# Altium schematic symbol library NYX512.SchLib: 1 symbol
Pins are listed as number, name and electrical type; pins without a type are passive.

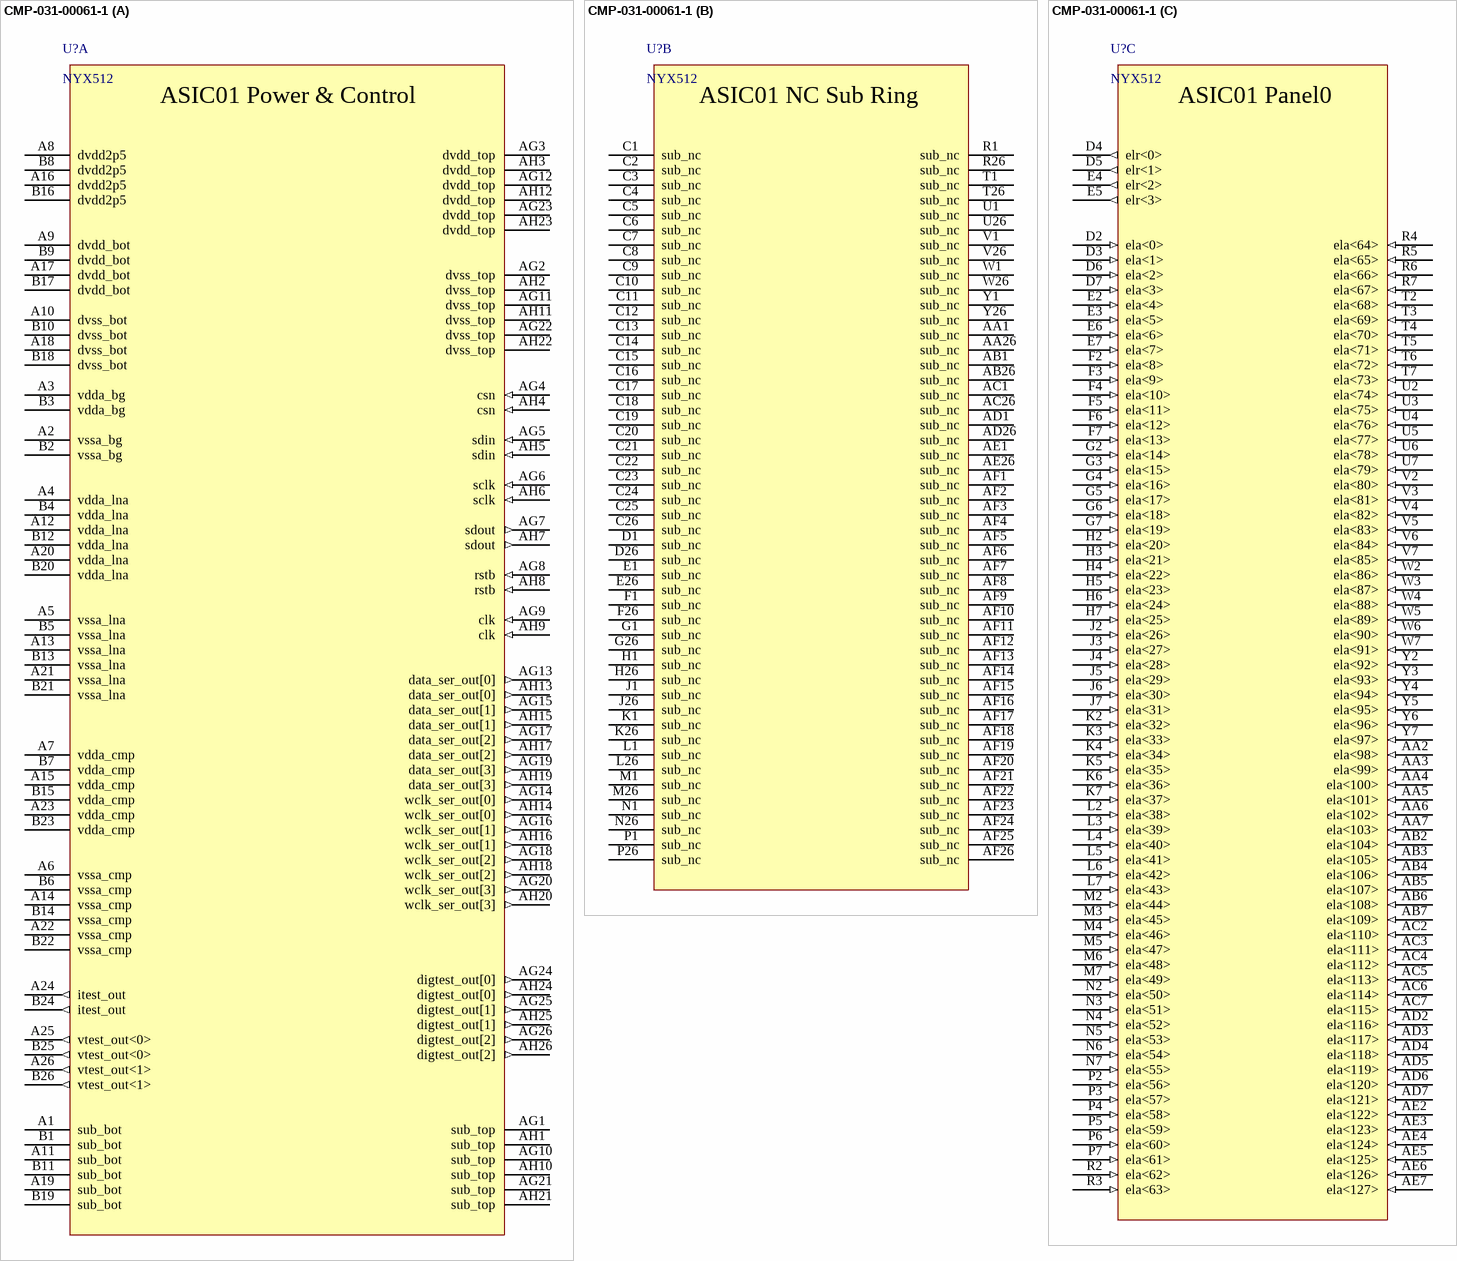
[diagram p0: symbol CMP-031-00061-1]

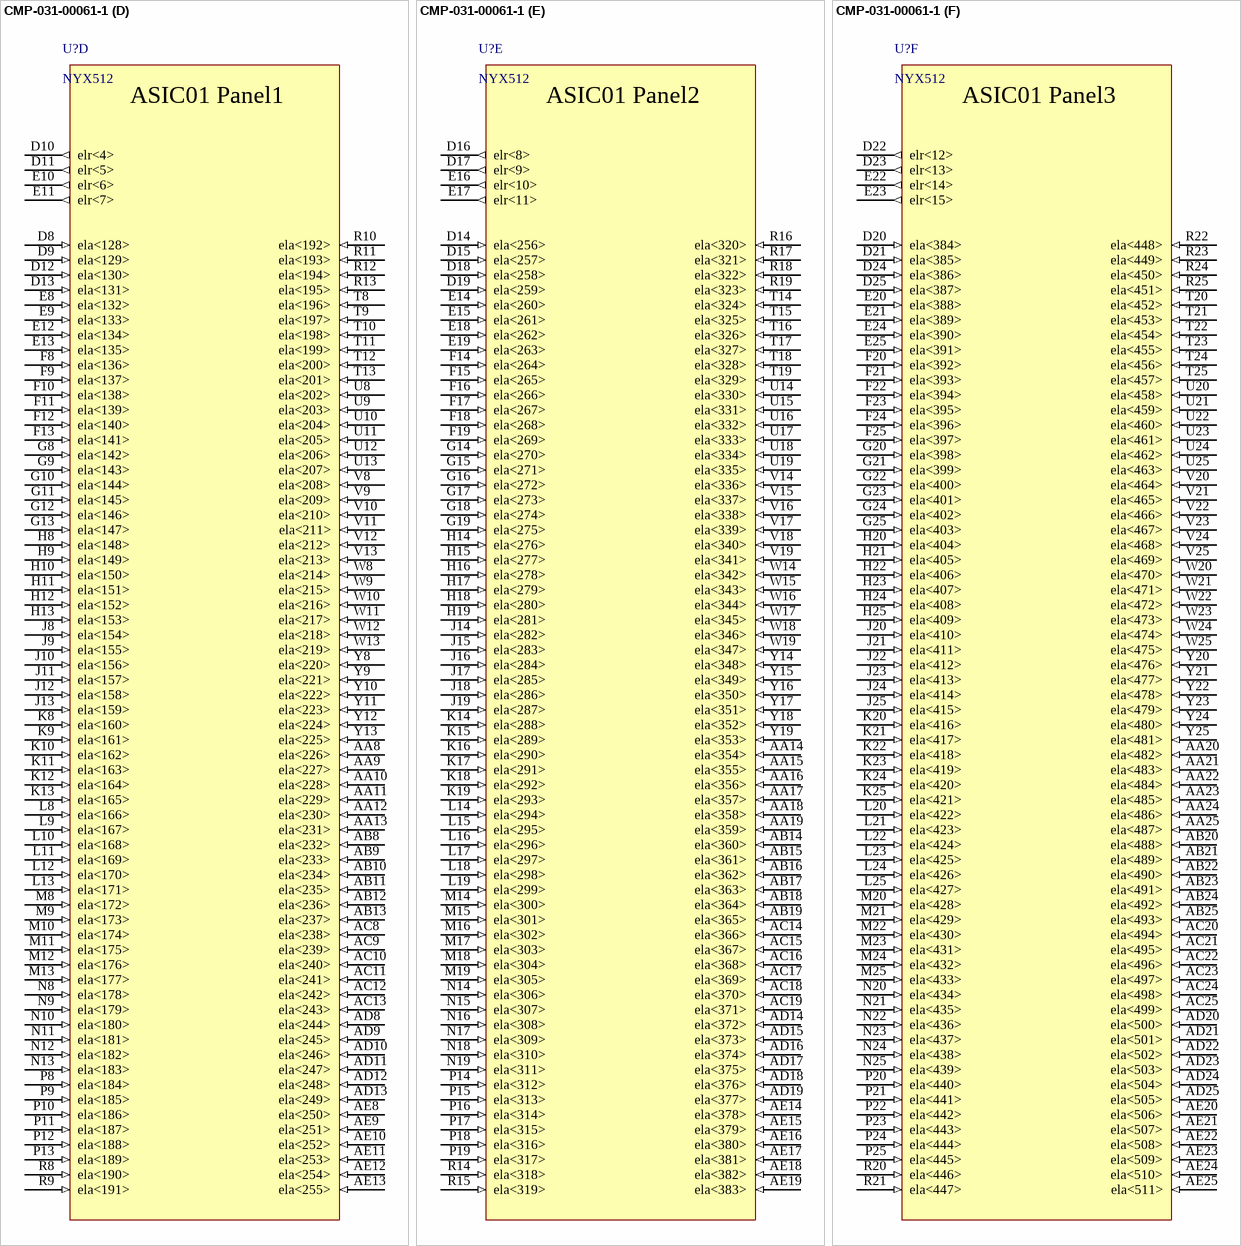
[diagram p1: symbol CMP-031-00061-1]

## CMP-031-00061-1
designator U?, comment NYX512
ASIC01 512 electrode neural recording IC; MPN: ASIC01(SCIENCE); ENG: Marat Rostov
footprint ASIC01_M-Footprint-1
part A pins: A1 sub_bot (power), A2 vssa_bg (power), A3 vdda_bg (power), A4 vdda_lna (power), A5 vssa_lna (power), A6 vssa_cmp (power), A7 vdda_cmp (power), A8 dvdd2p5 (power), A9 dvdd_bot (power), A10 dvss_bot (power), A11 sub_bot (power), A12 vdda_lna (power), A13 vssa_lna (power), A14 vssa_cmp (power), A15 vdda_cmp (power), A16 dvdd2p5 (power), A17 dvdd_bot (power), A18 dvss_bot (power), A19 sub_bot (power), A20 vdda_lna (power), A21 vssa_lna (power), A22 vssa_cmp (power), A23 vdda_cmp (power), A24 itest_out (out), A25 vtest_out<0> (out), A26 vtest_out<1> (out), AG1 sub_top (power), AG2 dvss_top (power), AG3 dvdd_top (power), AG4 csn (in), AG5 sdin (in), AG6 sclk (in), AG7 sdout (out), AG8 rstb (in), AG9 clk (in), AG10 sub_top (power), AG11 dvss_top (power), AG12 dvdd_top (power), AG13 data_ser_out[0] (out), AG14 wclk_ser_out[0] (out), AG15 data_ser_out[1] (out), AG16 wclk_ser_out[1] (out), AG17 data_ser_out[2] (out), AG18 wclk_ser_out[2] (out), AG19 data_ser_out[3] (out), AG20 wclk_ser_out[3] (out), AG21 sub_top (power), AG22 dvss_top (power), AG23 dvdd_top (power), AG24 digtest_out[0] (out), AG25 digtest_out[1] (out), AG26 digtest_out[2] (out), AH1 sub_top (power), AH2 dvss_top (power), AH3 dvdd_top (power), AH4 csn (in), AH5 sdin (in), AH6 sclk (in), AH7 sdout (out), AH8 rstb (in), AH9 clk (in), AH10 sub_top (power), AH11 dvss_top (power), AH12 dvdd_top (power), AH13 data_ser_out[0] (out), AH14 wclk_ser_out[0] (out), AH15 data_ser_out[1] (out), AH16 wclk_ser_out[1] (out), AH17 data_ser_out[2] (out), AH18 wclk_ser_out[2] (out), AH19 data_ser_out[3] (out), AH20 wclk_ser_out[3] (out), AH21 sub_top (power), AH22 dvss_top (power), AH23 dvdd_top (power), AH24 digtest_out[0] (out), AH25 digtest_out[1] (out), AH26 digtest_out[2] (out), B1 sub_bot (power), B2 vssa_bg (power), B3 vdda_bg (power), B4 vdda_lna (power), B5 vssa_lna (power), B6 vssa_cmp (power), B7 vdda_cmp (power), B8 dvdd2p5 (power), B9 dvdd_bot (power), B10 dvss_bot (power), B11 sub_bot (power), B12 vdda_lna (power), B13 vssa_lna (power), B14 vssa_cmp (power), B15 vdda_cmp (power), B16 dvdd2p5 (power), B17 dvdd_bot (power), B18 dvss_bot (power), B19 sub_bot (power), B20 vdda_lna (power), B21 vssa_lna (power), B22 vssa_cmp (power), B23 vdda_cmp (power), B24 itest_out (out), B25 vtest_out<0> (out), B26 vtest_out<1> (out)
part B pins: AA1 sub_nc, AA26 sub_nc, AB1 sub_nc, AB26 sub_nc, AC1 sub_nc, AC26 sub_nc, AD1 sub_nc, AD26 sub_nc, AE1 sub_nc, AE26 sub_nc, AF1 sub_nc, AF2 sub_nc, AF3 sub_nc, AF4 sub_nc, AF5 sub_nc, AF6 sub_nc, AF7 sub_nc, AF8 sub_nc, AF9 sub_nc, AF10 sub_nc, AF11 sub_nc, AF12 sub_nc, AF13 sub_nc, AF14 sub_nc, AF15 sub_nc, AF16 sub_nc, AF17 sub_nc, AF18 sub_nc, AF19 sub_nc, AF20 sub_nc, AF21 sub_nc, AF22 sub_nc, AF23 sub_nc, AF24 sub_nc, AF25 sub_nc, AF26 sub_nc, C1 sub_nc, C2 sub_nc, C3 sub_nc, C4 sub_nc, C5 sub_nc, C6 sub_nc, C7 sub_nc, C8 sub_nc, C9 sub_nc, C10 sub_nc, C11 sub_nc, C12 sub_nc, C13 sub_nc, C14 sub_nc, C15 sub_nc, C16 sub_nc, C17 sub_nc, C18 sub_nc, C19 sub_nc, C20 sub_nc, C21 sub_nc, C22 sub_nc, C23 sub_nc, C24 sub_nc, C25 sub_nc, C26 sub_nc, D1 sub_nc, D26 sub_nc, E1 sub_nc, E26 sub_nc, F1 sub_nc, F26 sub_nc, G1 sub_nc, G26 sub_nc, H1 sub_nc, H26 sub_nc, J1 sub_nc, J26 sub_nc, K1 sub_nc, K26 sub_nc, L1 sub_nc, L26 sub_nc, M1 sub_nc, M26 sub_nc, N1 sub_nc, N26 sub_nc, P1 sub_nc, P26 sub_nc, R1 sub_nc, R26 sub_nc, T1 sub_nc, T26 sub_nc, U1 sub_nc, U26 sub_nc, V1 sub_nc, V26 sub_nc, W1 sub_nc, W26 sub_nc, Y1 sub_nc, Y26 sub_nc
part C pins: AA2 ela<98> (in), AA3 ela<99> (in), AA4 ela<100> (in), AA5 ela<101> (in), AA6 ela<102> (in), AA7 ela<103> (in), AB2 ela<104> (in), AB3 ela<105> (in), AB4 ela<106> (in), AB5 ela<107> (in), AB6 ela<108> (in), AB7 ela<109> (in), AC2 ela<110> (in), AC3 ela<111> (in), AC4 ela<112> (in), AC5 ela<113> (in), AC6 ela<114> (in), AC7 ela<115> (in), AD2 ela<116> (in), AD3 ela<117> (in), AD4 ela<118> (in), AD5 ela<119> (in), AD6 ela<120> (in), AD7 ela<121> (in), AE2 ela<122> (in), AE3 ela<123> (in), AE4 ela<124> (in), AE5 ela<125> (in), AE6 ela<126> (in), AE7 ela<127> (in), D2 ela<0> (in), D3 ela<1> (in), D4 elr<0> (out), D5 elr<1> (out), D6 ela<2> (in), D7 ela<3> (in), E2 ela<4> (in), E3 ela<5> (in), E4 elr<2> (out), E5 elr<3> (out), E6 ela<6> (in), E7 ela<7> (in), F2 ela<8> (in), F3 ela<9> (in), F4 ela<10> (in), F5 ela<11> (in), F6 ela<12> (in), F7 ela<13> (in), G2 ela<14> (in), G3 ela<15> (in), G4 ela<16> (in), G5 ela<17> (in), G6 ela<18> (in), G7 ela<19> (in), H2 ela<20> (in), H3 ela<21> (in), H4 ela<22> (in), H5 ela<23> (in), H6 ela<24> (in), H7 ela<25> (in), J2 ela<26> (in), J3 ela<27> (in), J4 ela<28> (in), J5 ela<29> (in), J6 ela<30> (in), J7 ela<31> (in), K2 ela<32> (in), K3 ela<33> (in), K4 ela<34> (in), K5 ela<35> (in), K6 ela<36> (in), K7 ela<37> (in), L2 ela<38> (in), L3 ela<39> (in), L4 ela<40> (in), L5 ela<41> (in), L6 ela<42> (in), L7 ela<43> (in), M2 ela<44> (in), M3 ela<45> (in), M4 ela<46> (in), M5 ela<47> (in), M6 ela<48> (in), M7 ela<49> (in), N2 ela<50> (in), N3 ela<51> (in), N4 ela<52> (in), N5 ela<53> (in), N6 ela<54> (in), N7 ela<55> (in), P2 ela<56> (in), P3 ela<57> (in), P4 ela<58> (in), P5 ela<59> (in), P6 ela<60> (in), P7 ela<61> (in), R2 ela<62> (in), R3 ela<63> (in), R4 ela<64> (in), R5 ela<65> (in), R6 ela<66> (in), R7 ela<67> (in), T2 ela<68> (in), T3 ela<69> (in), T4 ela<70> (in), T5 ela<71> (in), T6 ela<72> (in), T7 ela<73> (in), U2 ela<74> (in), U3 ela<75> (in), U4 ela<76> (in), U5 ela<77> (in), U6 ela<78> (in), U7 ela<79> (in), V2 ela<80> (in), V3 ela<81> (in), V4 ela<82> (in), V5 ela<83> (in), V6 ela<84> (in), V7 ela<85> (in), W2 ela<86> (in), W3 ela<87> (in), W4 ela<88> (in), W5 ela<89> (in), W6 ela<90> (in), W7 ela<91> (in), Y2 ela<92> (in), Y3 ela<93> (in), Y4 ela<94> (in), Y5 ela<95> (in), Y6 ela<96> (in), Y7 ela<97> (in)
part D pins: AA8 ela<226> (in), AA9 ela<227> (in), AA10 ela<228> (in), AA11 ela<229> (in), AA12 ela<230> (in), AA13 ela<231> (in), AB8 ela<232> (in), AB9 ela<233> (in), AB10 ela<234> (in), AB11 ela<235> (in), AB12 ela<236> (in), AB13 ela<237> (in), AC8 ela<238> (in), AC9 ela<239> (in), AC10 ela<240> (in), AC11 ela<241> (in), AC12 ela<242> (in), AC13 ela<243> (in), AD8 ela<244> (in), AD9 ela<245> (in), AD10 ela<246> (in), AD11 ela<247> (in), AD12 ela<248> (in), AD13 ela<249> (in), AE8 ela<250> (in), AE9 ela<251> (in), AE10 ela<252> (in), AE11 ela<253> (in), AE12 ela<254> (in), AE13 ela<255> (in), D8 ela<128> (in), D9 ela<129> (in), D10 elr<4> (out), D11 elr<5> (out), D12 ela<130> (in), D13 ela<131> (in), E8 ela<132> (in), E9 ela<133> (in), E10 elr<6> (out), E11 elr<7> (out), E12 ela<134> (in), E13 ela<135> (in), F8 ela<136> (in), F9 ela<137> (in), F10 ela<138> (in), F11 ela<139> (in), F12 ela<140> (in), F13 ela<141> (in), G8 ela<142> (in), G9 ela<143> (in), G10 ela<144> (in), G11 ela<145> (in), G12 ela<146> (in), G13 ela<147> (in), H8 ela<148> (in), H9 ela<149> (in), H10 ela<150> (in), H11 ela<151> (in), H12 ela<152> (in), H13 ela<153> (in), J8 ela<154> (in), J9 ela<155> (in), J10 ela<156> (in), J11 ela<157> (in), J12 ela<158> (in), J13 ela<159> (in), K8 ela<160> (in), K9 ela<161> (in), K10 ela<162> (in), K11 ela<163> (in), K12 ela<164> (in), K13 ela<165> (in), L8 ela<166> (in), L9 ela<167> (in), L10 ela<168> (in), L11 ela<169> (in), L12 ela<170> (in), L13 ela<171> (in), M8 ela<172> (in), M9 ela<173> (in), M10 ela<174> (in), M11 ela<175> (in), M12 ela<176> (in), M13 ela<177> (in), N8 ela<178> (in), N9 ela<179> (in), N10 ela<180> (in), N11 ela<181> (in), N12 ela<182> (in), N13 ela<183> (in), P8 ela<184> (in), P9 ela<185> (in), P10 ela<186> (in), P11 ela<187> (in), P12 ela<188> (in), P13 ela<189> (in), R8 ela<190> (in), R9 ela<191> (in), R10 ela<192> (in), R11 ela<193> (in), R12 ela<194> (in), R13 ela<195> (in), T8 ela<196> (in), T9 ela<197> (in), T10 ela<198> (in), T11 ela<199> (in), T12 ela<200> (in), T13 ela<201> (in), U8 ela<202> (in), U9 ela<203> (in), U10 ela<204> (in), U11 ela<205> (in), U12 ela<206> (in), U13 ela<207> (in), V8 ela<208> (in), V9 ela<209> (in), V10 ela<210> (in), V11 ela<211> (in), V12 ela<212> (in), V13 ela<213> (in), W8 ela<214> (in), W9 ela<215> (in), W10 ela<216> (in), W11 ela<217> (in), W12 ela<218> (in), W13 ela<219> (in), Y8 ela<220> (in), Y9 ela<221> (in), Y10 ela<222> (in), Y11 ela<223> (in), Y12 ela<224> (in), Y13 ela<225> (in)
part E pins: AA14 ela<354> (in), AA15 ela<355> (in), AA16 ela<356> (in), AA17 ela<357> (in), AA18 ela<358> (in), AA19 ela<359> (in), AB14 ela<360> (in), AB15 ela<361> (in), AB16 ela<362> (in), AB17 ela<363> (in), AB18 ela<364> (in), AB19 ela<365> (in), AC14 ela<366> (in), AC15 ela<367> (in), AC16 ela<368> (in), AC17 ela<369> (in), AC18 ela<370> (in), AC19 ela<371> (in), AD14 ela<372> (in), AD15 ela<373> (in), AD16 ela<374> (in), AD17 ela<375> (in), AD18 ela<376> (in), AD19 ela<377> (in), AE14 ela<378> (in), AE15 ela<379> (in), AE16 ela<380> (in), AE17 ela<381> (in), AE18 ela<382> (in), AE19 ela<383> (in), D14 ela<256> (in), D15 ela<257> (in), D16 elr<8> (out), D17 elr<9> (out), D18 ela<258> (in), D19 ela<259> (in), E14 ela<260> (in), E15 ela<261> (in), E16 elr<10> (out), E17 elr<11> (out), E18 ela<262> (in), E19 ela<263> (in), F14 ela<264> (in), F15 ela<265> (in), F16 ela<266> (in), F17 ela<267> (in), F18 ela<268> (in), F19 ela<269> (in), G14 ela<270> (in), G15 ela<271> (in), G16 ela<272> (in), G17 ela<273> (in), G18 ela<274> (in), G19 ela<275> (in), H14 ela<276> (in), H15 ela<277> (in), H16 ela<278> (in), H17 ela<279> (in), H18 ela<280> (in), H19 ela<281> (in), J14 ela<282> (in), J15 ela<283> (in), J16 ela<284> (in), J17 ela<285> (in), J18 ela<286> (in), J19 ela<287> (in), K14 ela<288> (in), K15 ela<289> (in), K16 ela<290> (in), K17 ela<291> (in), K18 ela<292> (in), K19 ela<293> (in), L14 ela<294> (in), L15 ela<295> (in), L16 ela<296> (in), L17 ela<297> (in), L18 ela<298> (in), L19 ela<299> (in), M14 ela<300> (in), M15 ela<301> (in), M16 ela<302> (in), M17 ela<303> (in), M18 ela<304> (in), M19 ela<305> (in), N14 ela<306> (in), N15 ela<307> (in), N16 ela<308> (in), N17 ela<309> (in), N18 ela<310> (in), N19 ela<311> (in), P14 ela<312> (in), P15 ela<313> (in), P16 ela<314> (in), P17 ela<315> (in), P18 ela<316> (in), P19 ela<317> (in), R14 ela<318> (in), R15 ela<319> (in), R16 ela<320> (in), R17 ela<321> (in), R18 ela<322> (in), R19 ela<323> (in), T14 ela<324> (in), T15 ela<325> (in), T16 ela<326> (in), T17 ela<327> (in), T18 ela<328> (in), T19 ela<329> (in), U14 ela<330> (in), U15 ela<331> (in), U16 ela<332> (in), U17 ela<333> (in), U18 ela<334> (in), U19 ela<335> (in), V14 ela<336> (in), V15 ela<337> (in), V16 ela<338> (in), V17 ela<339> (in), V18 ela<340> (in), V19 ela<341> (in), W14 ela<342> (in), W15 ela<343> (in), W16 ela<344> (in), W17 ela<345> (in), W18 ela<346> (in), W19 ela<347> (in), Y14 ela<348> (in), Y15 ela<349> (in), Y16 ela<350> (in), Y17 ela<351> (in), Y18 ela<352> (in), Y19 ela<353> (in)
part F pins: AA20 ela<482> (in), AA21 ela<483> (in), AA22 ela<484> (in), AA23 ela<485> (in), AA24 ela<486> (in), AA25 ela<487> (in), AB20 ela<488> (in), AB21 ela<489> (in), AB22 ela<490> (in), AB23 ela<491> (in), AB24 ela<492> (in), AB25 ela<493> (in), AC20 ela<494> (in), AC21 ela<495> (in), AC22 ela<496> (in), AC23 ela<497> (in), AC24 ela<498> (in), AC25 ela<499> (in), AD20 ela<500> (in), AD21 ela<501> (in), AD22 ela<502> (in), AD23 ela<503> (in), AD24 ela<504> (in), AD25 ela<505> (in), AE20 ela<506> (in), AE21 ela<507> (in), AE22 ela<508> (in), AE23 ela<509> (in), AE24 ela<510> (in), AE25 ela<511> (in), D20 ela<384> (in), D21 ela<385> (in), D22 elr<12> (out), D23 elr<13> (out), D24 ela<386> (in), D25 ela<387> (in), E20 ela<388> (in), E21 ela<389> (in), E22 elr<14> (out), E23 elr<15> (out), E24 ela<390> (in), E25 ela<391> (in), F20 ela<392> (in), F21 ela<393> (in), F22 ela<394> (in), F23 ela<395> (in), F24 ela<396> (in), F25 ela<397> (in), G20 ela<398> (in), G21 ela<399> (in), G22 ela<400> (in), G23 ela<401> (in), G24 ela<402> (in), G25 ela<403> (in), H20 ela<404> (in), H21 ela<405> (in), H22 ela<406> (in), H23 ela<407> (in), H24 ela<408> (in), H25 ela<409> (in), J20 ela<410> (in), J21 ela<411> (in), J22 ela<412> (in), J23 ela<413> (in), J24 ela<414> (in), J25 ela<415> (in), K20 ela<416> (in), K21 ela<417> (in), K22 ela<418> (in), K23 ela<419> (in), K24 ela<420> (in), K25 ela<421> (in), L20 ela<422> (in), L21 ela<423> (in), L22 ela<424> (in), L23 ela<425> (in), L24 ela<426> (in), L25 ela<427> (in), M20 ela<428> (in), M21 ela<429> (in), M22 ela<430> (in), M23 ela<431> (in), M24 ela<432> (in), M25 ela<433> (in), N20 ela<434> (in), N21 ela<435> (in), N22 ela<436> (in), N23 ela<437> (in), N24 ela<438> (in), N25 ela<439> (in), P20 ela<440> (in), P21 ela<441> (in), P22 ela<442> (in), P23 ela<443> (in), P24 ela<444> (in), P25 ela<445> (in), R20 ela<446> (in), R21 ela<447> (in), R22 ela<448> (in), R23 ela<449> (in), R24 ela<450> (in), R25 ela<451> (in), T20 ela<452> (in), T21 ela<453> (in), T22 ela<454> (in), T23 ela<455> (in), T24 ela<456> (in), T25 ela<457> (in), U20 ela<458> (in), U21 ela<459> (in), U22 ela<460> (in), U23 ela<461> (in), U24 ela<462> (in), U25 ela<463> (in), V20 ela<464> (in), V21 ela<465> (in), V22 ela<466> (in), V23 ela<467> (in), V24 ela<468> (in), V25 ela<469> (in), W20 ela<470> (in), W21 ela<471> (in), W22 ela<472> (in), W23 ela<473> (in), W24 ela<474> (in), W25 ela<475> (in), Y20 ela<476> (in), Y21 ela<477> (in), Y22 ela<478> (in), Y23 ela<479> (in), Y24 ela<480> (in), Y25 ela<481> (in)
